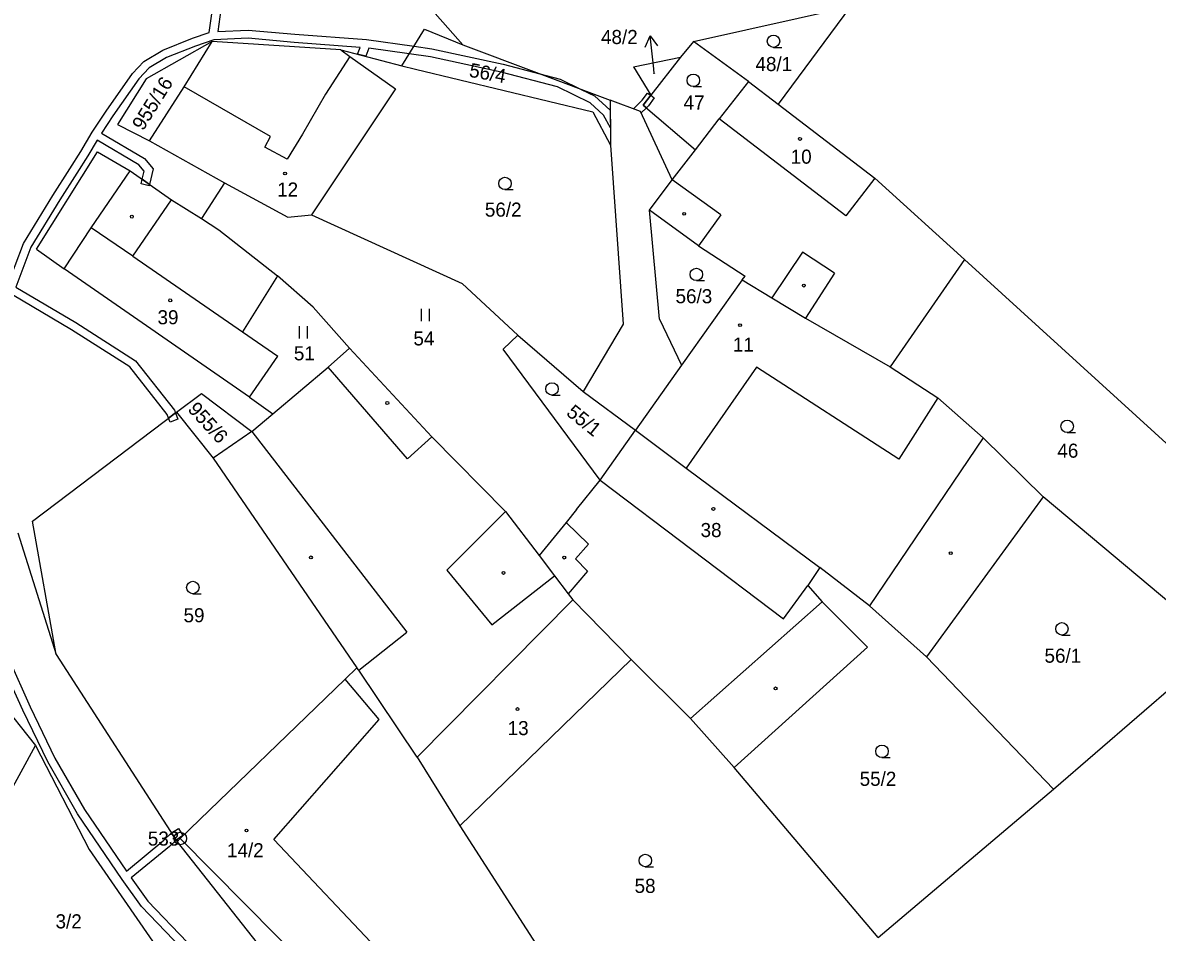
# Model space of a CAD drawing. Extents: x -749173 to -746119, y -1132678 to -1130338.
# Drawn here: x -747827.1 to -747690.2, y -1131098.8 to -1130989.1 of the extents above; entities that cross this region are included whole.
import ezdxf

# ---------------------------------------------------------------- set-up
doc = ezdxf.new("R2010")
doc.units = 0
for name, color, linetype in [('Vrstva 1', 7, 'Continuous'), ('Vrstva 16', 7, 'Continuous'), ('Vrstva 17', 7, 'Continuous'), ('Vrstva 18', 7, 'Continuous'), ('Vrstva 19', 7, 'Continuous'), ('Vrstva 24', 7, 'Continuous'), ('Vrstva 25', 7, 'Continuous'), ('Vrstva 3', 7, 'Continuous'), ('Vrstva 30', 7, 'Continuous'), ('Vrstva 37', 7, 'Continuous'), ('Vrstva 4', 7, 'Continuous')]:
    doc.layers.add(name, color=color, linetype=linetype)

msp = doc.modelspace()

# ---------------------------------------------------------------- linework, layer by layer
at = {"layer": 'Vrstva 1'}
msp.add_line((-747830.09, -1131070.64), (-747825.56, -1131076.31), dxfattribs=at)
for points in [[(-747774.01, -1130991.73), (-747779.16, -1130985.88)], [(-747746.19, -1130991.34), (-747727.26, -1130987.09)], [(-747727.26, -1130987.09), (-747735.98, -1130998.89)], [(-747781.36, -1130994.26), (-747778.63, -1130989.83)], [(-747778.63, -1130989.83), (-747774.01, -1130991.73)], [(-747804.24, -1130991.35), (-747812.24, -1130995.82)], [(-747807.64, -1130996.81), (-747804.24, -1130991.35)], [(-747788.75, -1130992.33), (-747804.24, -1130991.35)], [(-747788.75, -1130992.33), (-747787.65, -1130993.13)], [(-747788.75, -1130992.33), (-747781.36, -1130994.26)], [(-747774.01, -1130991.73), (-747756.26, -1130998.42)], [(-747746.19, -1130991.34), (-747747.76, -1130993.24)], [(-747739.57, -1130996.15), (-747746.19, -1130991.34)], [(-747787.65, -1130993.13), (-747782.13, -1130997.05)], [(-747753.43, -1130994.41), (-747747.76, -1130993.24)], [(-747747.76, -1130993.24), (-747751.34, -1130997.82)], [(-747781.36, -1130994.26), (-747779.73, -1130994.69)], [(-747779.73, -1130994.69), (-747758.32, -1130999.81)], [(-747753.43, -1130994.41), (-747751.34, -1130997.82)], [(-747812.24, -1130995.82), (-747815.68, -1131001.33)], [(-747739.57, -1130996.15), (-747743.1, -1131000.68)], [(-747739.57, -1130996.15), (-747735.98, -1130998.89)], [(-747811.81, -1131003.33), (-747807.64, -1130996.81)], [(-747782.13, -1130997.05), (-747792.29, -1131012.25)], [(-747751.34, -1130997.82), (-747752.28, -1130999)], [(-747752.58, -1130999.77), (-747756.26, -1130998.42)], [(-747756.26, -1130998.42), (-747756.19, -1131003.83)], [(-747752.28, -1130999), (-747745.97, -1131004.41)], [(-747735.98, -1130998.89), (-747724.31, -1131007.81)], [(-747758.32, -1130999.81), (-747756.19, -1131003.83)], [(-747748.76, -1131008.04), (-747752.58, -1130999.77)], [(-747815.68, -1131001.33), (-747811.81, -1131003.33)], [(-747745.97, -1131004.41), (-747743.1, -1131000.68)], [(-747811.81, -1131003.33), (-747802.79, -1131008.38)], [(-747825.46, -1131016.4), (-747818.08, -1131004.63)], [(-747818.08, -1131004.63), (-747814.14, -1131006.93)], [(-747756.19, -1131003.83), (-747754.69, -1131025.46)], [(-747748.76, -1131008.04), (-747745.97, -1131004.41)], [(-747814.14, -1131006.93), (-747809.15, -1131010.43)], [(-747802.79, -1131008.38), (-747805.54, -1131012.68)], [(-747802.79, -1131008.38), (-747795.15, -1131012.54)], [(-747751.5, -1131011.7), (-747748.76, -1131008.04)], [(-747724.31, -1131007.81), (-747713.52, -1131017.65)], [(-747809.15, -1131010.43), (-747805.54, -1131012.68)], [(-747805.54, -1131012.68), (-747803.44, -1131014.07)], [(-747795.15, -1131012.54), (-747792.29, -1131012.25)], [(-747792.29, -1131012.25), (-747774.1, -1131020.52)], [(-747745.61, -1131016), (-747751.5, -1131011.7)], [(-747750.3, -1131024.84), (-747751.5, -1131011.7)], [(-747803.44, -1131014.07), (-747796.37, -1131019.61)], [(-747825.46, -1131016.4), (-747822.1, -1131018.76)], [(-747745.61, -1131016), (-747739.97, -1131019.67)], [(-747713.52, -1131017.65), (-747722.47, -1131030.61)], [(-747713.52, -1131017.65), (-747672.07, -1131055.39)], [(-747799.75, -1131034.27), (-747822.1, -1131018.76)], [(-747796.37, -1131019.61), (-747800.58, -1131026.38)], [(-747792.06, -1131023.38), (-747796.37, -1131019.61)], [(-747740.32, -1131020.09), (-747739.97, -1131019.67)], [(-747774.1, -1131020.52), (-747767.4, -1131026.79)], [(-747740.32, -1131020.09), (-747747.65, -1131030.39)], [(-747740.32, -1131020.09), (-747736.76, -1131022.27)], [(-747736.76, -1131022.27), (-747732.68, -1131024.74)], [(-747787.69, -1131028.33), (-747792.06, -1131023.38)], [(-747750.3, -1131024.84), (-747747.65, -1131030.39)], [(-747732.68, -1131024.74), (-747722.47, -1131030.61)], [(-747800.58, -1131026.38), (-747796.33, -1131029.3)], [(-747754.69, -1131025.46), (-747759.51, -1131033.58)], [(-747769.17, -1131028.48), (-747767.4, -1131026.79)], [(-747767.4, -1131026.79), (-747759.51, -1131033.58)], [(-747799.75, -1131034.27), (-747796.33, -1131029.3)], [(-747790.26, -1131030.63), (-747787.69, -1131028.33)], [(-747787.69, -1131028.33), (-747777.74, -1131039.06)], [(-747757.45, -1131044.29), (-747769.17, -1131028.48)], [(-747796.93, -1131036.25), (-747790.26, -1131030.63)], [(-747722.47, -1131030.61), (-747716.71, -1131034.32)], [(-747808.56, -1131036.05), (-747805.55, -1131033.82)], [(-747805.55, -1131033.82), (-747799.49, -1131038.4)], [(-747799.75, -1131034.27), (-747796.93, -1131036.25)], [(-747759.51, -1131033.58), (-747753.2, -1131038.23)], [(-747711.26, -1131039.16), (-747716.71, -1131034.32)], [(-747825.94, -1131049.2), (-747808.56, -1131036.05)], [(-747808.56, -1131036.05), (-747804.15, -1131041.6)], [(-747799.49, -1131038.4), (-747796.93, -1131036.25)], [(-747799.49, -1131038.4), (-747804.15, -1131041.6)], [(-747757.45, -1131044.29), (-747753.2, -1131038.23)], [(-747753.2, -1131038.23), (-747747.07, -1131042.82)], [(-747777.74, -1131039.06), (-747768.86, -1131048.06)], [(-747704.02, -1131046.27), (-747711.26, -1131039.16)], [(-747804.15, -1131041.6), (-747786.82, -1131066.91)], [(-747747.07, -1131042.82), (-747730.95, -1131054.8)], [(-747760.29, -1131047.82), (-747757.45, -1131044.29)], [(-747704.02, -1131046.27), (-747718.1, -1131065.6)], [(-747682.65, -1131064.18), (-747704.02, -1131046.27)], [(-747768.86, -1131048.06), (-747764.81, -1131053.38)], [(-747760.29, -1131047.82), (-747761.54, -1131049.36)], [(-747823.07, -1131065.32), (-747825.94, -1131049.2)], [(-747761.54, -1131049.36), (-747764.81, -1131053.38)], [(-747827.69, -1131050.62), (-747823.07, -1131065.32)], [(-747764.81, -1131053.38), (-747762.97, -1131055.8)], [(-747730.95, -1131054.8), (-747732.42, -1131057)], [(-747724.97, -1131059.43), (-747730.95, -1131054.8)], [(-747762.97, -1131055.8), (-747761.31, -1131057.99)], [(-747761.31, -1131057.99), (-747760.77, -1131058.7)], [(-747732.42, -1131057), (-747730.67, -1131058.96)], [(-747753.72, -1131065.9), (-747760.77, -1131058.7)], [(-747730.67, -1131058.96), (-747725.22, -1131064.42)], [(-747718.1, -1131065.6), (-747724.97, -1131059.43)], [(-747741.27, -1131078.96), (-747725.22, -1131064.42)], [(-747702.76, -1131081.57), (-747682.65, -1131064.18)], [(-747823.07, -1131065.32), (-747808.48, -1131087.91)], [(-747774.37, -1131086), (-747753.72, -1131065.9)], [(-747746.57, -1131073.05), (-747753.72, -1131065.9)], [(-747718.1, -1131065.6), (-747702.76, -1131081.57)], [(-747786.82, -1131066.91), (-747788.23, -1131068.27)], [(-747786.55, -1131067.19), (-747786.82, -1131066.91)], [(-747779.51, -1131077.69), (-747786.55, -1131067.19)], [(-747788.23, -1131068.27), (-747808.1, -1131087.52)], [(-747746.57, -1131073.05), (-747741.27, -1131078.96)], [(-747832.27, -1131088.57), (-747825.56, -1131076.31)], [(-747825.56, -1131076.31), (-747819.11, -1131088.84)], [(-747779.51, -1131077.69), (-747774.37, -1131086)], [(-747723.91, -1131099.47), (-747741.27, -1131078.96)], [(-747723.91, -1131099.47), (-747702.76, -1131081.57)], [(-747774.37, -1131086), (-747761.8, -1131105.54)], [(-747808.1, -1131087.52), (-747808.48, -1131087.91)], [(-747808.48, -1131087.91), (-747794.01, -1131106.24)], [(-747819.11, -1131088.84), (-747809.11, -1131103.29)]]:
    msp.add_lwpolyline(points, dxfattribs=at)
at = {"layer": 'Vrstva 16'}
msp.add_line((-747752.04, -1130992.02), (-747751.44, -1130990.65), dxfattribs=at)
for points in [[(-747750.99, -1130994.62), (-747751.44, -1130990.65), (-747750.55, -1130991.85)], [(-747750.92, -1130995.23), (-747750.99, -1130994.62)]]:
    msp.add_lwpolyline(points, dxfattribs=at)
at = {"layer": 'Vrstva 24'}
msp.add_line((-747808.15, -1131087.52), (-747808.05, -1131087.52), dxfattribs=at)
msp.add_circle((-747808.1, -1131087.52), 0.756, dxfattribs=at)
at = {"layer": 'Vrstva 25'}
for p, q in [((-747736.54, -1130992.05), (-747735.54, -1130992.05)), ((-747746.22, -1130996.77), (-747745.22, -1130996.77)), ((-747768.94, -1131009.21), (-747767.94, -1131009.21)), ((-747745.85, -1131020.19), (-747744.85, -1131020.19)), ((-747779.04, -1131023.58), (-747779.04, -1131025.08)), ((-747778.04, -1131025.08), (-747778.04, -1131023.58)), ((-747793.75, -1131025.67), (-747793.75, -1131027.17)), ((-747792.75, -1131027.17), (-747792.75, -1131025.67)), ((-747763.27, -1131034.01), (-747762.27, -1131034.01)), ((-747701.12, -1131038.52), (-747700.12, -1131038.52)), ((-747806.59, -1131057.97), (-747805.59, -1131057.97)), ((-747701.75, -1131062.96), (-747700.75, -1131062.96)), ((-747723.46, -1131077.74), (-747722.46, -1131077.74)), ((-747752.01, -1131090.92), (-747751.01, -1131090.92))]:
    msp.add_line(p, q, dxfattribs=at)
for centre, radius in [((-747736.54, -1130991.3), 0.75), ((-747746.22, -1130996.02), 0.75), ((-747733.35, -1131003.09), 0.175), ((-747795.46, -1131007.26), 0.175), ((-747768.94, -1131008.46), 0.75), ((-747813.95, -1131012.47), 0.175), ((-747747.32, -1131012.13), 0.175), ((-747745.85, -1131019.44), 0.75), ((-747732.88, -1131020.79), 0.175), ((-747809.31, -1131022.57), 0.175), ((-747740.58, -1131025.56), 0.175), ((-747763.27, -1131033.26), 0.75), ((-747783.13, -1131034.96), 0.175), ((-747701.12, -1131037.77), 0.75), ((-747743.8, -1131047.74), 0.175), ((-747792.35, -1131053.59), 0.175), ((-747761.79, -1131053.62), 0.175), ((-747715.16, -1131053.08), 0.175), ((-747769.12, -1131055.47), 0.175), ((-747806.59, -1131057.22), 0.75), ((-747701.75, -1131062.21), 0.75), ((-747736.29, -1131069.4), 0.175), ((-747767.42, -1131071.89), 0.175), ((-747723.46, -1131076.99), 0.75), ((-747800.12, -1131086.55), 0.175), ((-747752.01, -1131090.17), 0.75)]:
    msp.add_circle(centre, radius, dxfattribs=at)
at = {"layer": 'Vrstva 3'}
for points in [[(-747787.65, -1130993.13), (-747790.59, -1130997.7)], [(-747787.65, -1130993.13), (-747782.13, -1130997.05)], [(-747739.57, -1130996.15), (-747743.1, -1131000.68)], [(-747739.57, -1130996.15), (-747735.98, -1130998.89)], [(-747811.81, -1131003.33), (-747807.64, -1130996.81)], [(-747797.23, -1131002.81), (-747807.64, -1130996.81)], [(-747790.59, -1130997.7), (-747793.38, -1131002.53)], [(-747782.13, -1130997.05), (-747792.29, -1131012.25)], [(-747735.98, -1130998.89), (-747724.31, -1131007.81)], [(-747727.8, -1131012.38), (-747743.1, -1131000.68)], [(-747811.81, -1131003.33), (-747802.79, -1131008.38)], [(-747797.92, -1131004.08), (-747797.23, -1131002.81)], [(-747793.38, -1131002.53), (-747795.2, -1131005.55)], [(-747795.2, -1131005.55), (-747797.92, -1131004.08)], [(-747802.79, -1131008.38), (-747795.15, -1131012.54)], [(-747724.31, -1131007.81), (-747727.8, -1131012.38)], [(-747795.15, -1131012.54), (-747792.29, -1131012.25)], [(-747822.1, -1131018.76), (-747818.85, -1131013.81)], [(-747813.84, -1131017.24), (-747818.85, -1131013.81)], [(-747813.84, -1131017.24), (-747800.58, -1131026.38)], [(-747799.75, -1131034.27), (-747822.1, -1131018.76)], [(-747740.32, -1131020.09), (-747747.65, -1131030.39)], [(-747740.32, -1131020.09), (-747736.76, -1131022.27)], [(-747736.76, -1131022.27), (-747732.68, -1131024.74)], [(-747732.68, -1131024.74), (-747722.47, -1131030.61)], [(-747800.58, -1131026.38), (-747796.33, -1131029.3)], [(-747799.75, -1131034.27), (-747796.33, -1131029.3)], [(-747747.65, -1131030.39), (-747753.2, -1131038.23)], [(-747738.59, -1131030.64), (-747747.07, -1131042.82)], [(-747721.43, -1131041.73), (-747738.59, -1131030.64)], [(-747722.47, -1131030.61), (-747716.71, -1131034.32)], [(-747716.71, -1131034.32), (-747721.43, -1131041.73)], [(-747757.45, -1131044.29), (-747753.2, -1131038.23)], [(-747753.2, -1131038.23), (-747747.07, -1131042.82)], [(-747753.2, -1131038.23), (-747747.07, -1131042.82)], [(-747747.07, -1131042.82), (-747730.95, -1131054.8)], [(-747757.45, -1131044.29), (-747735.34, -1131061.01)], [(-747730.95, -1131054.8), (-747732.42, -1131057)], [(-747735.34, -1131061.01), (-747732.42, -1131057)], [(-747760.77, -1131058.7), (-747779.51, -1131077.69)], [(-747753.72, -1131065.9), (-747760.77, -1131058.7)], [(-747774.37, -1131086), (-747753.72, -1131065.9)], [(-747788.23, -1131068.27), (-747808.1, -1131087.52)], [(-747784.12, -1131073.14), (-747788.23, -1131068.27)], [(-747796.8, -1131087.65), (-747784.12, -1131073.14)], [(-747779.51, -1131077.69), (-747774.37, -1131086)], [(-747788.64, -1131107.19), (-747808.1, -1131087.52)], [(-747783.76, -1131101.49), (-747796.8, -1131087.65)]]:
    msp.add_lwpolyline(points, dxfattribs=at)
at = {"layer": 'Vrstva 30'}
for points in [[(-747804.61, -1130990.26), (-747803.87, -1130984.91)], [(-747802.85, -1130984.79), (-747803.58, -1130990.11)], [(-747810.2, -1130992.38), (-747806.64, -1130990.95)], [(-747806.64, -1130990.95), (-747804.61, -1130990.26)], [(-747799.93, -1130990.95), (-747804.07, -1130991.12)], [(-747803.58, -1130990.11), (-747799.91, -1130989.95)], [(-747794.37, -1130991.45), (-747799.93, -1130990.95)], [(-747799.91, -1130989.95), (-747794.29, -1130990.45)], [(-747794.29, -1130990.45), (-747785.64, -1130991.1)], [(-747812.51, -1130993.73), (-747810.2, -1130992.38)], [(-747806.28, -1130991.89), (-747809.76, -1130993.28)], [(-747804.07, -1130991.12), (-747806.28, -1130991.89)], [(-747786.4, -1130992.04), (-747794.37, -1130991.45)], [(-747786.71, -1130992.86), (-747786.4, -1130992.04)], [(-747785.37, -1130992.14), (-747785.74, -1130993.12)], [(-747785.64, -1130991.1), (-747779.9, -1130991.9)], [(-747780.48, -1130992.83), (-747785.37, -1130992.14)], [(-747779.9, -1130991.9), (-747777.76, -1130992.2)], [(-747777.76, -1130992.2), (-747769.17, -1130994.07)], [(-747813.88, -1130995.21), (-747812.51, -1130993.73)], [(-747809.76, -1130993.28), (-747811.87, -1130994.51)], [(-747785.74, -1130993.12), (-747786.71, -1130992.86)], [(-747777.94, -1130993.18), (-747780.48, -1130992.83)], [(-747769.4, -1130995.05), (-747777.94, -1130993.18)], [(-747811.87, -1130994.51), (-747813.1, -1130995.84)], [(-747762.62, -1130996.81), (-747769.4, -1130995.05)], [(-747769.17, -1130994.07), (-747764.72, -1130995.23)], [(-747817.06, -1130999.76), (-747813.88, -1130995.21)], [(-747813.1, -1130995.84), (-747816.24, -1131000.32)], [(-747764.72, -1130995.23), (-747762.28, -1130995.87)], [(-747762.28, -1130995.87), (-747759.74, -1130997.11)], [(-747758.68, -1130998.74), (-747762.62, -1130996.81)], [(-747759.74, -1130997.11), (-747758.12, -1130997.9)], [(-747752.37, -1130998.43), (-747751.73, -1130997.55)], [(-747751.88, -1130999.35), (-747752.28, -1130999), (-747751.34, -1130997.82)], [(-747751.34, -1130997.82), (-747752.28, -1130999)], [(-747751.73, -1130997.55), (-747751.34, -1130997.82)], [(-747751.34, -1130997.82), (-747750.92, -1130998.14)], [(-747757.05, -1131000.24), (-747758.68, -1130998.74)], [(-747758.12, -1130997.9), (-747756.24, -1130999.63)], [(-747753.44, -1130999.45), (-747752.37, -1130998.43)], [(-747752.28, -1130999), (-747751.88, -1130999.35)], [(-747751.61, -1130999.09), (-747751.88, -1130999.35)], [(-747750.92, -1130998.14), (-747751.61, -1130999.09)], [(-747818.73, -1131002.28), (-747817.06, -1130999.76)], [(-747816.24, -1131000.32), (-747817.59, -1131002.38)], [(-747756.22, -1131001.74), (-747757.05, -1131000.24)], [(-747756.24, -1130999.63), (-747756.22, -1131001.74)], [(-747752.5, -1130999.94), (-747752.58, -1130999.77), (-747753.44, -1130999.45)], [(-747751.88, -1130999.35), (-747752.5, -1130999.94)], [(-747820.1, -1131004.6), (-747818.73, -1131002.28)], [(-747818.13, -1131003.22), (-747819.24, -1131005.12)], [(-747813.09, -1131006.23), (-747818.13, -1131003.22)], [(-747817.59, -1131002.38), (-747812.43, -1131005.47)], [(-747821.43, -1131006.7), (-747820.1, -1131004.6)], [(-747819.24, -1131005.12), (-747820.59, -1131007.24)], [(-747812.43, -1131005.47), (-747811.38, -1131006.71)], [(-747823.48, -1131009.9), (-747821.43, -1131006.7)], [(-747820.59, -1131007.24), (-747822.64, -1131010.44)], [(-747812.46, -1131006.97), (-747813.09, -1131006.23)], [(-747812.69, -1131007.95), (-747812.46, -1131006.97)], [(-747811.38, -1131006.71), (-747811.8, -1131008.57)], [(-747812.82, -1131008.52), (-747812.69, -1131007.95)], [(-747811.84, -1131008.75), (-747812.82, -1131008.52)], [(-747812.69, -1131007.95), (-747811.8, -1131008.57)], [(-747811.8, -1131008.57), (-747812.69, -1131007.95)], [(-747811.8, -1131008.57), (-747811.84, -1131008.75)], [(-747827.02, -1131015.71), (-747823.48, -1131009.9)], [(-747822.64, -1131010.44), (-747826.12, -1131016.15)], [(-747829.04, -1131021), (-747827.02, -1131015.71)], [(-747826.12, -1131016.15), (-747827.96, -1131020.96)], [(-747827.96, -1131020.96), (-747820.69, -1131025.26)], [(-747821.21, -1131026.12), (-747828.33, -1131021.91)], [(-747814.18, -1131030.6), (-747821.21, -1131026.12)], [(-747820.69, -1131025.26), (-747813.5, -1131029.86)], [(-747809.67, -1131036.33), (-747814.18, -1131030.6)], [(-747813.5, -1131029.86), (-747808.79, -1131035.83)], [(-747809.51, -1131036.77), (-747808.67, -1131036.14)], [(-747808.67, -1131036.14), (-747809.51, -1131036.77)], [(-747808.79, -1131035.83), (-747808.67, -1131036.14)], [(-747808.67, -1131036.14), (-747808.39, -1131036.92)], [(-747809.51, -1131036.77), (-747809.67, -1131036.33)], [(-747809.32, -1131037.27), (-747809.51, -1131036.77)], [(-747808.39, -1131036.92), (-747809.32, -1131037.27)], [(-747827.11, -1131072.04), (-747829.76, -1131066.15)], [(-747828.84, -1131065.77), (-747826.21, -1131071.62)], [(-747826.21, -1131071.62), (-747823.22, -1131077.82)], [(-747824.1, -1131078.28), (-747827.11, -1131072.04)], [(-747820.51, -1131084.54), (-747824.1, -1131078.28)], [(-747823.22, -1131077.82), (-747819.65, -1131084.02)], [(-747819.65, -1131084.02), (-747814.61, -1131091.46)], [(-747815.13, -1131092.47), (-747820.51, -1131084.54)], [(-747809.17, -1131086.85), (-747808.31, -1131086.31)], [(-747808.31, -1131086.31), (-747807.79, -1131087.17)], [(-747814.61, -1131091.46), (-747810.07, -1131087.71)], [(-747810.07, -1131087.71), (-747809.17, -1131086.85)], [(-747808.61, -1131087.7), (-747809.41, -1131088.47)], [(-747809.17, -1131086.85), (-747808.61, -1131087.7)], [(-747808.61, -1131087.7), (-747809.17, -1131086.85)], [(-747807.79, -1131087.17), (-747808.61, -1131087.7)], [(-747809.41, -1131088.47), (-747814.04, -1131092.28)], [(-747814.04, -1131092.28), (-747812.01, -1131095.09)], [(-747812.77, -1131095.73), (-747815.13, -1131092.47)], [(-747807.96, -1131100.76), (-747812.77, -1131095.73)], [(-747812.01, -1131095.09), (-747807.24, -1131100.06)]]:
    msp.add_lwpolyline(points, dxfattribs=at)
at = {"layer": 'Vrstva 37'}
for centre in [(-747733.35, -1131003.09), (-747795.46, -1131007.26), (-747809.31, -1131022.57), (-747740.58, -1131025.56), (-747743.8, -1131047.74), (-747767.42, -1131071.89), (-747800.12, -1131086.55)]:
    msp.add_circle(centre, 0.175, dxfattribs=at)
at = {"layer": 'Vrstva 4'}
for points in [[(-747787.65, -1130993.13), (-747790.59, -1130997.7)], [(-747797.23, -1131002.81), (-747807.64, -1130996.81)], [(-747790.59, -1130997.7), (-747793.38, -1131002.53)], [(-747727.8, -1131012.38), (-747743.1, -1131000.68)], [(-747797.92, -1131004.08), (-747797.23, -1131002.81)], [(-747793.38, -1131002.53), (-747795.2, -1131005.55)], [(-747795.2, -1131005.55), (-747797.92, -1131004.08)], [(-747818.85, -1131013.81), (-747814.14, -1131006.93)], [(-747742.91, -1131012.25), (-747748.76, -1131008.04)], [(-747724.31, -1131007.81), (-747727.8, -1131012.38)], [(-747813.84, -1131017.24), (-747809.15, -1131010.43)], [(-747742.91, -1131012.25), (-747745.61, -1131016)], [(-747822.1, -1131018.76), (-747818.85, -1131013.81)], [(-747813.84, -1131017.24), (-747818.85, -1131013.81)], [(-747733.04, -1131016.75), (-747736.76, -1131022.27)], [(-747729.17, -1131019.31), (-747733.04, -1131016.75)], [(-747813.84, -1131017.24), (-747800.58, -1131026.38)], [(-747729.17, -1131019.31), (-747732.68, -1131024.74)], [(-747780.7, -1131041.7), (-747790.26, -1131030.63)], [(-747747.65, -1131030.39), (-747753.2, -1131038.23)], [(-747738.59, -1131030.64), (-747747.07, -1131042.82)], [(-747721.43, -1131041.73), (-747738.59, -1131030.64)], [(-747716.71, -1131034.32), (-747721.43, -1131041.73)], [(-747799.49, -1131038.4), (-747780.78, -1131062.62)], [(-747777.74, -1131039.06), (-747780.7, -1131041.7)], [(-747711.26, -1131039.16), (-747724.97, -1131059.43)], [(-747757.45, -1131044.29), (-747735.34, -1131061.01)], [(-747768.86, -1131048.06), (-747775.97, -1131055.14)], [(-747758.85, -1131051.98), (-747761.54, -1131049.36)], [(-747760.42, -1131053.77), (-747758.85, -1131051.98)], [(-747758.98, -1131055.25), (-747760.42, -1131053.77)], [(-747775.97, -1131055.14), (-747770.54, -1131061.71)], [(-747758.98, -1131055.25), (-747761.31, -1131057.99)], [(-747770.54, -1131061.71), (-747762.97, -1131055.8)], [(-747735.34, -1131061.01), (-747732.42, -1131057)], [(-747760.77, -1131058.7), (-747779.51, -1131077.69)], [(-747730.67, -1131058.96), (-747746.57, -1131073.05)], [(-747786.55, -1131067.19), (-747780.78, -1131062.62)], [(-747784.12, -1131073.14), (-747788.23, -1131068.27)], [(-747796.8, -1131087.65), (-747784.12, -1131073.14)], [(-747788.64, -1131107.19), (-747808.1, -1131087.52)], [(-747783.76, -1131101.49), (-747796.8, -1131087.65)]]:
    msp.add_lwpolyline(points, dxfattribs=at)

# ---------------------------------------------------------------- texts
at = {"layer": 'Vrstva 16'}
msp.add_text('48/2', height=1.7, dxfattribs=at).set_placement((-747757.35, -1130991.64))
at = {"layer": 'Vrstva 17'}
msp.add_text('533', height=1.7, dxfattribs=at).set_placement((-747812.02, -1131088.37))
at = {"layer": 'Vrstva 18'}
for s, height, p in [('48/1', 1.7, (-747738.72, -1130994.9)), ('48/2', 0.1, (-747751.07, -1130995.23)), ('47', 1.7, (-747747.39, -1130999.54)), ('56/2', 1.7, (-747771.36, -1131012.47)), ('56/3', 1.7, (-747748.36, -1131022.92)), ('54', 1.7, (-747779.98, -1131028.01)), ('51', 1.7, (-747794.4, -1131029.81)), ('46', 1.7, (-747702.3, -1131041.56)), ('59', 1.7, (-747807.71, -1131061.42)), ('56/1', 1.7, (-747703.85, -1131066.3)), ('55/2', 1.7, (-747726.15, -1131081.16)), ('58', 1.7, (-747753.3, -1131094.08)), ('3/2', 1.7, (-747823.15, -1131098.36))]:
    msp.add_text(s, height=height, dxfattribs=at).set_placement(p)
for s, rotation, p in [('56/4', 349.3652, (-747773.35, -1130995.57)), ('955/16', 58.0189, (-747812.59, -1131002.19)), ('955/6', 312.417, (-747807.3, -1131035.79)), ('55/1', 320.9155, (-747761.65, -1131036.33))]:
    msp.add_text(s, height=1.7, rotation=rotation, dxfattribs=at).set_placement(p)
at = {"layer": 'Vrstva 19'}
for s, p in [('10', (-747734.47, -1131006.08)), ('12', (-747796.42, -1131010.05)), ('39', (-747810.85, -1131025.46)), ('11', (-747741.44, -1131028.76)), ('38', (-747745.34, -1131051.14)), ('13', (-747768.61, -1131075.04)), ('14/2', (-747802.47, -1131089.78))]:
    msp.add_text(s, height=1.7, dxfattribs=at).set_placement(p)

doc.saveas('drawing.dxf')
